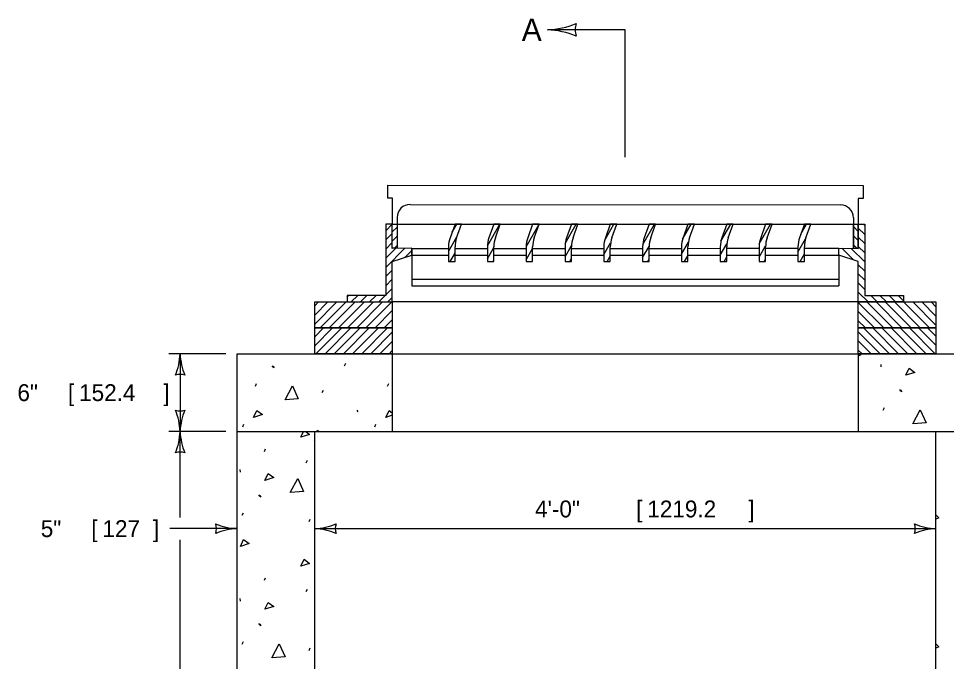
# Model space of a CAD drawing. Extents: x 49991.4 to 50057, y 49987.6 to 50011.4.
# Drawn here: x 50041.919 to 50045.224, y 49995.965 to 49998.253 of the extents above; entities that cross this region are included whole.
import ezdxf

# ---------------------------------------------------------------- set-up
doc = ezdxf.new("R2010")
doc.units = 0
for name, color, linetype in [('Level 1', 7, 'Continuous'), ('Level 2', 7, 'Continuous'), ('Level 3', 7, 'Continuous'), ('Level 6', 7, 'Continuous')]:
    doc.layers.add(name, color=color, linetype=linetype)

msp = doc.modelspace()

# ---------------------------------------------------------------- linework, layer by layer
at = {"layer": 'Level 1'}
for p, q in [((50043.2333, 49997.6608), (50044.9272, 49997.6593)), ((50043.2333, 49997.6608), (50043.2333, 49997.6147)), ((50044.9272, 49997.6593), (50044.9272, 49997.6132)), ((50043.2333, 49997.6147), (50043.2506, 49997.6147)), ((50043.2506, 49997.6147), (50043.2506, 49997.5211)), ((50044.9272, 49997.6132), (50044.9099, 49997.6132)), ((50044.9099, 49997.6132), (50044.9099, 49997.5211)), ((50043.314, 49997.5916), (50044.8466, 49997.5903)), ((50043.2679, 49997.5455), (50043.2679, 49997.5211)), ((50044.8926, 49997.5442), (50044.8926, 49997.4359)), ((50043.2275, 49997.4981), (50043.2506, 49997.5211)), ((50043.2506, 49997.4938), (50043.2679, 49997.5111)), ((50043.2679, 49997.5211), (50043.2679, 49997.4359)), ((50043.2679, 49997.5211), (50044.8926, 49997.5211)), ((50043.4636, 49997.493), (50043.4799, 49997.5211)), ((50043.5891, 49997.4445), (50043.6333, 49997.5211)), ((50043.7274, 49997.4412), (50043.7734, 49997.5211)), ((50043.8663, 49997.4526), (50043.9058, 49997.5211)), ((50044.007, 49997.465), (50044.0394, 49997.5211)), ((50044.1425, 49997.449), (50044.1841, 49997.5211)), ((50044.2844, 49997.4681), (50044.315, 49997.5211)), ((50044.4207, 49997.4604), (50044.4557, 49997.5211)), ((50044.5575, 49997.4513), (50044.5978, 49997.5211)), ((50044.7054, 49997.4855), (50044.7259, 49997.5211)), ((50044.8926, 49997.513), (50044.9099, 49997.4957)), ((50044.9099, 49997.5077), (50044.933, 49997.4847)), ((50044.9292, 49997.5211), (50044.933, 49997.5173)), ((50043.2275, 49997.4655), (50043.2506, 49997.4885)), ((50043.2506, 49997.4612), (50043.2679, 49997.4785)), ((50043.4508, 49997.4247), (50043.4806, 49997.4763)), ((50044.6953, 49997.4219), (50044.7226, 49997.4692)), ((50044.8926, 49997.4804), (50044.9099, 49997.4631)), ((50044.9099, 49997.4751), (50044.933, 49997.4521)), ((50043.2275, 49997.4329), (50043.2506, 49997.4559)), ((50043.2275, 49997.3677), (50043.2954, 49997.4355)), ((50043.2275, 49997.4003), (50043.2621, 49997.4349)), ((50043.2579, 49997.4359), (50043.2679, 49997.4459)), ((50043.3197, 49997.4346), (50043.451, 49997.4347)), ((50043.3197, 49997.4346), (50043.3197, 49997.3021)), ((50043.4741, 49997.4348), (50043.5891, 49997.4349)), ((50043.5891, 49997.3984), (50043.6121, 49997.4383)), ((50043.6121, 49997.4349), (50043.7274, 49997.435)), ((50043.7274, 49997.3951), (50043.7504, 49997.4351)), ((50043.7504, 49997.435), (50043.8659, 49997.4351)), ((50043.8656, 49997.4054), (50043.8888, 49997.4454)), ((50043.8887, 49997.4351), (50044.0039, 49997.4352)), ((50044.0039, 49997.4136), (50044.028, 49997.4553)), ((50044.027, 49997.4352), (50044.1422, 49997.4353)), ((50044.1422, 49997.4024), (50044.1652, 49997.4423)), ((50044.1652, 49997.4353), (50044.2807, 49997.4354)), ((50044.2805, 49997.4152), (50044.3049, 49997.4575)), ((50044.3035, 49997.4354), (50044.4189, 49997.4355)), ((50044.4187, 49997.4109), (50044.4424, 49997.4518)), ((50044.442, 49997.4356), (50044.5572, 49997.4357)), ((50044.557, 49997.4043), (50044.5801, 49997.4443)), ((50044.5802, 49997.4357), (50044.6955, 49997.4358)), ((50044.7185, 49997.4358), (50044.8408, 49997.4359)), ((50044.8515, 49997.4358), (50044.8931, 49997.3941)), ((50044.8847, 49997.4351), (50044.933, 49997.3869)), ((50044.8926, 49997.4478), (50044.9058, 49997.4346)), ((50044.9099, 49997.4425), (50044.933, 49997.4195)), ((50043.2962, 49997.4038), (50043.3197, 49997.4273)), ((50043.3197, 49997.4116), (50043.4508, 49997.4116)), ((50043.4566, 49997.3885), (50043.4739, 49997.4185)), ((50043.4739, 49997.4116), (50043.5891, 49997.4116)), ((50043.6121, 49997.4116), (50043.7274, 49997.4116)), ((50043.7504, 49997.4116), (50043.8656, 49997.4116)), ((50043.8825, 49997.3885), (50043.8887, 49997.3992)), ((50043.8887, 49997.4116), (50044.0039, 49997.4116)), ((50044.0161, 49997.3885), (50044.027, 49997.4074)), ((50044.027, 49997.4116), (50044.1422, 49997.4116)), ((50044.1652, 49997.4116), (50044.2805, 49997.4116)), ((50044.2917, 49997.3885), (50044.3035, 49997.409)), ((50044.3035, 49997.4116), (50044.4187, 49997.4116)), ((50044.4324, 49997.3885), (50044.4418, 49997.4047)), ((50044.4418, 49997.4116), (50044.557, 49997.4116)), ((50044.5745, 49997.3885), (50044.5801, 49997.3981)), ((50044.5801, 49997.4116), (50044.6953, 49997.4116)), ((50044.7027, 49997.3885), (50044.7183, 49997.4157)), ((50044.7183, 49997.4116), (50044.8408, 49997.4116)), ((50044.8408, 49997.4116), (50044.8408, 49997.3021)), ((50043.61, 49997.3885), (50043.6121, 49997.3922)), ((50043.7502, 49997.3885), (50043.7504, 49997.389)), ((50044.1608, 49997.3885), (50044.1652, 49997.3962)), ((50044.9099, 49997.3773), (50044.933, 49997.3543)), ((50043.2275, 49997.3351), (50043.2506, 49997.3581)), ((50044.9099, 49997.3448), (50044.933, 49997.3217)), ((50043.2275, 49997.3025), (50043.2506, 49997.3255)), ((50043.3197, 49997.3252), (50044.8408, 49997.3252)), ((50043.3197, 49997.3021), (50044.8408, 49997.3021)), ((50044.9099, 49997.3122), (50044.933, 49997.2891)), ((50043.0893, 49997.262), (50043.0948, 49997.2676)), ((50043.1044, 49997.2445), (50043.1274, 49997.2676)), ((50043.137, 49997.2445), (50043.16, 49997.2676)), ((50043.1696, 49997.2445), (50043.1926, 49997.2676)), ((50043.2021, 49997.2445), (50043.2252, 49997.2676)), ((50043.2275, 49997.2699), (50043.2506, 49997.293)), ((50044.9099, 49997.2796), (50044.945, 49997.2445)), ((50044.9545, 49997.2676), (50044.9776, 49997.2445)), ((50044.9871, 49997.2676), (50045.0102, 49997.2445)), ((50045.0197, 49997.2676), (50045.0427, 49997.2445)), ((50045.0523, 49997.2676), (50045.0712, 49997.2486)), ((50042.974, 49997.1654), (50043.0531, 49997.2445)), ((50042.974, 49997.198), (50043.0205, 49997.2445)), ((50042.974, 49997.2306), (50042.9879, 49997.2445)), ((50042.9935, 49997.1523), (50043.0857, 49997.2445)), ((50043.0261, 49997.1523), (50043.1183, 49997.2445)), ((50043.0587, 49997.1523), (50043.1509, 49997.2445)), ((50043.0913, 49997.1523), (50043.1835, 49997.2445)), ((50043.1239, 49997.1523), (50043.2161, 49997.2445)), ((50043.1565, 49997.1523), (50043.2487, 49997.2445)), ((50043.2347, 49997.2445), (50043.2506, 49997.2604)), ((50044.9099, 49997.2445), (50043.2506, 49997.2445)), ((50044.9099, 49997.247), (50044.9124, 49997.2445)), ((50044.9099, 49997.243), (50045.0006, 49997.1523)), ((50044.941, 49997.2445), (50045.0332, 49997.1523)), ((50044.9736, 49997.2445), (50045.0658, 49997.1523)), ((50045.0062, 49997.2445), (50045.0984, 49997.1523)), ((50045.0388, 49997.2445), (50045.131, 49997.1523)), ((50045.0714, 49997.2445), (50045.1636, 49997.1523)), ((50045.104, 49997.2445), (50045.1865, 49997.162)), ((50045.1366, 49997.2445), (50045.1865, 49997.1946)), ((50045.1692, 49997.2445), (50045.1865, 49997.2272)), ((50043.1891, 49997.1523), (50043.2506, 49997.2138)), ((50044.9099, 49997.2105), (50044.968, 49997.1523)), ((50043.2217, 49997.1523), (50043.2506, 49997.1813)), ((50044.9099, 49997.1779), (50044.9354, 49997.1523)), ((50042.974, 49997.0884), (50043.038, 49997.1523)), ((50042.974, 49997.121), (50043.0054, 49997.1523)), ((50042.9784, 49997.0601), (50043.0706, 49997.1523)), ((50043.011, 49997.0601), (50043.1032, 49997.1523)), ((50043.0436, 49997.0601), (50043.1358, 49997.1523)), ((50043.0762, 49997.0601), (50043.1684, 49997.1523)), ((50043.1088, 49997.0601), (50043.201, 49997.1523)), ((50043.1414, 49997.0601), (50043.2335, 49997.1523)), ((50043.174, 49997.0601), (50043.2506, 49997.1368)), ((50044.9099, 49997.1388), (50044.9886, 49997.0601)), ((50044.929, 49997.1523), (50045.0212, 49997.0601)), ((50044.9616, 49997.1523), (50045.0538, 49997.0601)), ((50044.9942, 49997.1523), (50045.0864, 49997.0601)), ((50045.0268, 49997.1523), (50045.119, 49997.0601)), ((50045.0594, 49997.1523), (50045.1516, 49997.0601)), ((50045.092, 49997.1523), (50045.1841, 49997.0601)), ((50045.1246, 49997.1523), (50045.1865, 49997.0904)), ((50045.1571, 49997.1523), (50045.1865, 49997.123)), ((50043.2065, 49997.0601), (50043.2506, 49997.1042)), ((50044.9099, 49997.1062), (50044.956, 49997.0601)), ((50043.2391, 49997.0601), (50043.2506, 49997.0716)), ((50044.9099, 49997.0736), (50044.9234, 49997.0601)), ((50042.6975, 49997.0601), (50043.2506, 49997.0601)), ((50042.6975, 49994.5712), (50042.6975, 49997.0601)), ((50043.2506, 49997.0601), (50043.2506, 49996.7836)), ((50043.2506, 49997.0601), (50044.9099, 49997.0601)), ((50044.9099, 49997.0601), (50045.463, 49997.0601)), ((50044.9099, 49997.0601), (50044.9099, 49996.7836)), ((50042.8213, 49997.0179), (50042.8253, 49997.012)), ((50042.8253, 49997.0156), (50042.8292, 49997.0097)), ((50043.0807, 49997.0179), (50043.0846, 49997.0267)), ((50044.9901, 49997.0222), (50044.991, 49997.0133)), ((50042.7634, 49996.945), (50042.7673, 49996.9539)), ((50043.2339, 49996.945), (50043.2378, 49996.9539)), ((50043.0011, 49996.9224), (50043.005, 49996.9313)), ((50045.0571, 49996.9329), (50045.061, 49996.927)), ((50045.061, 49996.9306), (50045.065, 49996.9247)), ((50043.1239, 49996.8596), (50043.1278, 49996.8537)), ((50043.2506, 49996.8414), (50043.227, 49996.834)), ((50044.9991, 49996.8601), (50045.0031, 49996.8689)), ((50042.7176, 49996.8005), (50042.7215, 49996.8093)), ((50043.1881, 49996.8005), (50043.1921, 49996.8093)), ((50042.6975, 49996.7836), (50045.463, 49996.7836)), ((50042.9246, 49996.7635), (50042.9343, 49996.7836)), ((50042.974, 49994.8477), (50042.974, 49996.7836)), ((50045.1865, 49994.8477), (50045.1865, 49996.7836)), ((50042.9732, 49996.7508), (50042.974, 49996.7523)), ((50042.7948, 49996.7129), (50042.7987, 49996.7217)), ((50042.9441, 49996.6726), (50042.948, 49996.6814)), ((50042.7071, 49996.6479), (50042.7081, 49996.6391)), ((50042.7741, 49996.5586), (50042.7781, 49996.5527)), ((50042.7781, 49996.5564), (50042.782, 49996.5505)), ((50042.7162, 49996.4858), (50042.7201, 49996.4947)), ((50042.9539, 49996.4632), (50042.9579, 49996.4721)), ((50042.7948, 49996.254), (50042.7987, 49996.2628)), ((50042.9441, 49996.2137), (50042.948, 49996.2226)), ((50042.7071, 49996.189), (50042.7081, 49996.1802)), ((50042.7741, 49996.0998), (50042.7781, 49996.0939)), ((50042.7781, 49996.0975), (50042.782, 49996.0916)), ((50042.7162, 49996.0269), (50042.7201, 49996.0358)), ((50042.9539, 49996.0044), (50042.9579, 49996.0132))]:
    msp.add_line(p, q, dxfattribs=at)
for points in [[(50043.2506, 49997.2445), (50043.2506, 49997.3885), (50043.3197, 49997.4116), (50043.3197, 49997.436), (50043.2506, 49997.4346), (50043.2506, 49997.5211), (50043.2275, 49997.5211), (50043.2275, 49997.2676), (50043.0893, 49997.2676), (50043.0893, 49997.2445)], [(50043.2506, 49997.5211), (50043.2679, 49997.5211), (50043.2679, 49997.4359), (50043.2506, 49997.4359)], [(50044.9099, 49997.2445), (50044.9099, 49997.3885), (50044.8408, 49997.4116), (50044.8408, 49997.436), (50044.9099, 49997.4346), (50044.9099, 49997.5211), (50044.933, 49997.5211), (50044.933, 49997.2676), (50045.0712, 49997.2676), (50045.0712, 49997.2445)], [(50044.8926, 49997.5211), (50044.9099, 49997.5211), (50044.9099, 49997.4346), (50044.8926, 49997.4346)], [(50042.974, 49997.2445), (50043.2506, 49997.2445), (50043.2506, 49997.1523), (50042.974, 49997.1523)], [(50044.9099, 49997.2445), (50045.1865, 49997.2445), (50045.1865, 49997.1523), (50044.9099, 49997.1523)], [(50042.974, 49997.1523), (50043.2506, 49997.1523), (50043.2506, 49997.0601), (50042.974, 49997.0601)], [(50044.9099, 49997.1523), (50045.1865, 49997.1523), (50045.1865, 49997.0601), (50044.9099, 49997.0601)]]:
    msp.add_lwpolyline(points, close=True, dxfattribs=at)
for points in [[(50043.4794, 49997.4729), (50043.4969, 49997.5211), (50043.4739, 49997.5211), (50043.4739, 49997.5211), (50043.4564, 49997.4729)], [(50043.6177, 49997.4729), (50043.6352, 49997.5211), (50043.6121, 49997.5211), (50043.6121, 49997.5211), (50043.5946, 49997.4729)], [(50043.756, 49997.4729), (50043.7735, 49997.5211), (50043.7504, 49997.5211), (50043.7504, 49997.5211), (50043.7329, 49997.4729)], [(50043.8942, 49997.4729), (50043.9117, 49997.5211), (50043.8887, 49997.5211), (50043.8887, 49997.5211), (50043.8712, 49997.4729)], [(50044.0325, 49997.4729), (50044.05, 49997.5211), (50044.027, 49997.5211), (50044.027, 49997.5211), (50044.0095, 49997.4729)], [(50044.1708, 49997.4729), (50044.1883, 49997.5211), (50044.1652, 49997.5211), (50044.1652, 49997.5211), (50044.1477, 49997.4729)], [(50044.3091, 49997.4729), (50044.3266, 49997.5211), (50044.3035, 49997.5211), (50044.3035, 49997.5211), (50044.286, 49997.4729)], [(50044.4473, 49997.4729), (50044.4648, 49997.5211), (50044.4418, 49997.5211), (50044.4418, 49997.5211), (50044.4243, 49997.4729)], [(50044.5856, 49997.4729), (50044.6031, 49997.5211), (50044.5801, 49997.5211), (50044.5801, 49997.5211), (50044.5626, 49997.4729)], [(50044.7239, 49997.4729), (50044.7414, 49997.5211), (50044.7183, 49997.5211), (50044.7183, 49997.5211), (50044.7008, 49997.4729)], [(50043.4508, 49997.4414), (50043.4508, 49997.3885), (50043.4739, 49997.3885), (50043.4739, 49997.4414)], [(50043.5891, 49997.4414), (50043.5891, 49997.3885), (50043.6121, 49997.3885), (50043.6121, 49997.4414)], [(50043.7274, 49997.4414), (50043.7274, 49997.3885), (50043.7504, 49997.3885), (50043.7504, 49997.4414)], [(50043.8656, 49997.4414), (50043.8656, 49997.3885), (50043.8887, 49997.3885), (50043.8887, 49997.4414)], [(50044.0039, 49997.4414), (50044.0039, 49997.3885), (50044.027, 49997.3885), (50044.027, 49997.4414)], [(50044.1422, 49997.4414), (50044.1422, 49997.3885), (50044.1652, 49997.3885), (50044.1652, 49997.4414)], [(50044.2805, 49997.4414), (50044.2805, 49997.3885), (50044.3035, 49997.3885), (50044.3035, 49997.4414)], [(50044.4187, 49997.4414), (50044.4187, 49997.3885), (50044.4418, 49997.3885), (50044.4418, 49997.4414)], [(50044.557, 49997.4414), (50044.557, 49997.3885), (50044.5801, 49997.3885), (50044.5801, 49997.4414)], [(50044.6953, 49997.4414), (50044.6953, 49997.3885), (50044.7183, 49997.3885), (50044.7183, 49997.4414)], [(50044.9154, 49997.0601), (50044.919, 49997.0565), (50044.9099, 49997.0523)], [(50045.0797, 49996.984), (50045.0915, 49997.0085), (50045.1111, 49996.9938), (50045.0797, 49996.984)], [(50042.8685, 49996.8959), (50042.895, 49996.946), (50042.9156, 49996.8999), (50042.8695, 49996.8959)], [(50042.7565, 49996.834), (50042.7683, 49996.8586), (50042.7879, 49996.8439), (50042.7565, 49996.834)], [(50043.227, 49996.834), (50043.2388, 49996.8586), (50043.2506, 49996.8498)], [(50045.1043, 49996.811), (50045.1308, 49996.861), (50045.1514, 49996.8149), (50045.1052, 49996.811)], [(50042.9424, 49996.7836), (50042.9561, 49996.7733), (50042.9246, 49996.7635)], [(50042.9813, 49996.7836), (50042.9836, 49996.7884), (50042.99, 49996.7836)], [(50042.7968, 49996.6097), (50042.8085, 49996.6343), (50042.8282, 49996.6195), (50042.7968, 49996.6097)], [(50042.8872, 49996.5662), (50042.9137, 49996.6163), (50042.9344, 49996.5702), (50042.8882, 49996.5662)], [(50045.1865, 49996.4873), (50045.1973, 49996.4761), (50045.1865, 49996.4711)], [(50042.7093, 49996.3748), (50042.7211, 49996.3994), (50042.7407, 49996.3846), (50042.7093, 49996.3748)], [(50042.9246, 49996.3046), (50042.9364, 49996.3292), (50042.9561, 49996.3144), (50042.9246, 49996.3046)], [(50042.7968, 49996.1508), (50042.8085, 49996.1754), (50042.8282, 49996.1607), (50042.7968, 49996.1508)], [(50042.8213, 49995.9778), (50042.8478, 49996.0279), (50042.8685, 49995.9818), (50042.8223, 49995.9778)], [(50045.1865, 49996.0284), (50045.1973, 49996.0172), (50045.1865, 49996.0122)]]:
    msp.add_lwpolyline(points, dxfattribs=at)
for centre, radius, start, end in [((50043.314, 49997.5455), 0.0461, 89.9504, 180), ((50044.8465, 49997.5442), 0.0461, 0, 89.9504), ((50043.543, 49997.4414), 0.0922, 160.0169, 180), ((50043.566, 49997.4414), 0.0922, 160.0169, 180), ((50043.6813, 49997.4414), 0.0922, 160.0169, 180), ((50043.7043, 49997.4414), 0.0922, 160.0169, 180), ((50043.8195, 49997.4414), 0.0922, 160.0169, 180), ((50043.8426, 49997.4414), 0.0922, 160.0169, 180), ((50043.9578, 49997.4414), 0.0922, 160.0169, 180), ((50043.9809, 49997.4414), 0.0922, 160.0169, 180), ((50044.0961, 49997.4414), 0.0922, 160.0169, 180), ((50044.1191, 49997.4414), 0.0922, 160.0169, 180), ((50044.2344, 49997.4414), 0.0922, 160.0169, 180), ((50044.2574, 49997.4414), 0.0922, 160.0169, 180), ((50044.3726, 49997.4414), 0.0922, 160.0169, 180), ((50044.3957, 49997.4414), 0.0922, 160.0169, 180), ((50044.5109, 49997.4414), 0.0922, 160.0169, 180), ((50044.534, 49997.4414), 0.0922, 160.0169, 180), ((50044.6492, 49997.4414), 0.0922, 160.0169, 180), ((50044.6722, 49997.4414), 0.0922, 160.0169, 180), ((50044.7875, 49997.4414), 0.0922, 160.0169, 180), ((50044.8105, 49997.4414), 0.0922, 160.0169, 180)]:
    msp.add_arc(centre, radius, start, end, dxfattribs=at)
at = {"layer": 'Level 3'}
for p, q in [((50042.6575, 49997.0601), (50042.4548, 49997.0601)), ((50042.4948, 49997.0601), (50042.4948, 49996.7836)), ((50042.6575, 49996.7836), (50042.4548, 49996.7836)), ((50042.4948, 49996.4779), (50042.4948, 49996.7836)), ((50042.6975, 49996.4379), (50042.4579, 49996.4379)), ((50042.974, 49996.4379), (50045.1865, 49996.4379)), ((50042.4948, 49994.8477), (50042.4948, 49996.3979))]:
    msp.add_line(p, q, dxfattribs=at)
for centre, radius, start, end in [((50042.2727, 49997.0693), 0.2223, 337.456, 357.6395), ((50042.7275, 49997.0716), 0.233, 182.8273, 202.0772), ((50042.4948, 49996.9319), 0.0548, 72.1388, 107.8612), ((50042.4948, 49996.9118), 0.0548, 252.1388, 287.8612), ((50042.2621, 49996.7721), 0.233, 2.8273, 22.0772), ((50042.7169, 49996.7744), 0.2223, 157.456, 177.6395), ((50042.2727, 49996.7927), 0.2223, 337.456, 357.6395), ((50042.7275, 49996.7951), 0.233, 182.8273, 202.0772), ((50042.4948, 49996.6554), 0.0548, 72.1388, 107.8612), ((50042.7066, 49996.66), 0.2223, 247.456, 267.6395), ((50042.5693, 49996.4379), 0.0548, 342.1388, 17.8612), ((50042.9625, 49996.6706), 0.233, 272.8273, 292.0772), ((50043.1023, 49996.4379), 0.0548, 162.1388, 197.8612), ((50045.1956, 49996.66), 0.2223, 247.456, 267.6395), ((50045.0582, 49996.4379), 0.0548, 342.1388, 17.8612), ((50042.709, 49996.2052), 0.233, 92.8273, 112.0772), ((50042.9649, 49996.2158), 0.2223, 67.456, 87.6395), ((50045.198, 49996.2052), 0.233, 92.8273, 112.0772)]:
    msp.add_arc(centre, radius, start, end, dxfattribs=at)
at = {"layer": 'Level 6'}
for p, q in [((50044.0803, 49998.2132), (50043.8037, 49998.2132)), ((50044.0803, 49997.7601), (50044.0803, 49998.2132))]:
    msp.add_line(p, q, dxfattribs=at)
msp.add_lwpolyline([(50043.8037, 49998.2132), (50043.8037, 49998.2132)], dxfattribs=at)
for centre, radius, start, end in [((50043.7884, 49998.5234), 0.3107, 272.8273, 292.0772), ((50043.9747, 49998.2132), 0.073, 162.1388, 197.8612), ((50043.7915, 49997.917), 0.2964, 67.456, 87.6395)]:
    msp.add_arc(centre, radius, start, end, dxfattribs=at)

# ---------------------------------------------------------------- texts
at = {"layer": 'Level 2'}
for s, height, p in [('A', 0.08, (50043.7114, 49998.1732)), ('[', 0.06, (50044.119, 49996.4779)), (']', 0.06, (50044.5187, 49996.4779)), ('4\'-0" ', 0.06, (50043.759, 49996.4779)), ('1219.2', 0.06, (50044.1587, 49996.4779)), ('5" ', 0.06, (50041.9984, 49996.4079)), ('[', 0.06, (50042.1784, 49996.4079)), ('127', 0.06, (50042.2181, 49996.4079)), (']', 0.06, (50042.3981, 49996.4079))]:
    msp.add_text(s, height=height, dxfattribs=at).set_placement(p)
for s, p in [('6" ', (50041.9153, 49996.8919)), ('[', (50042.0953, 49996.8919)), ('152.4', (50042.135, 49996.8919)), (']', (50042.435, 49996.8919))]:
    msp.add_text(s, height=0.06, rotation=360, dxfattribs=at).set_placement(p)

doc.saveas('drawing.dxf')
